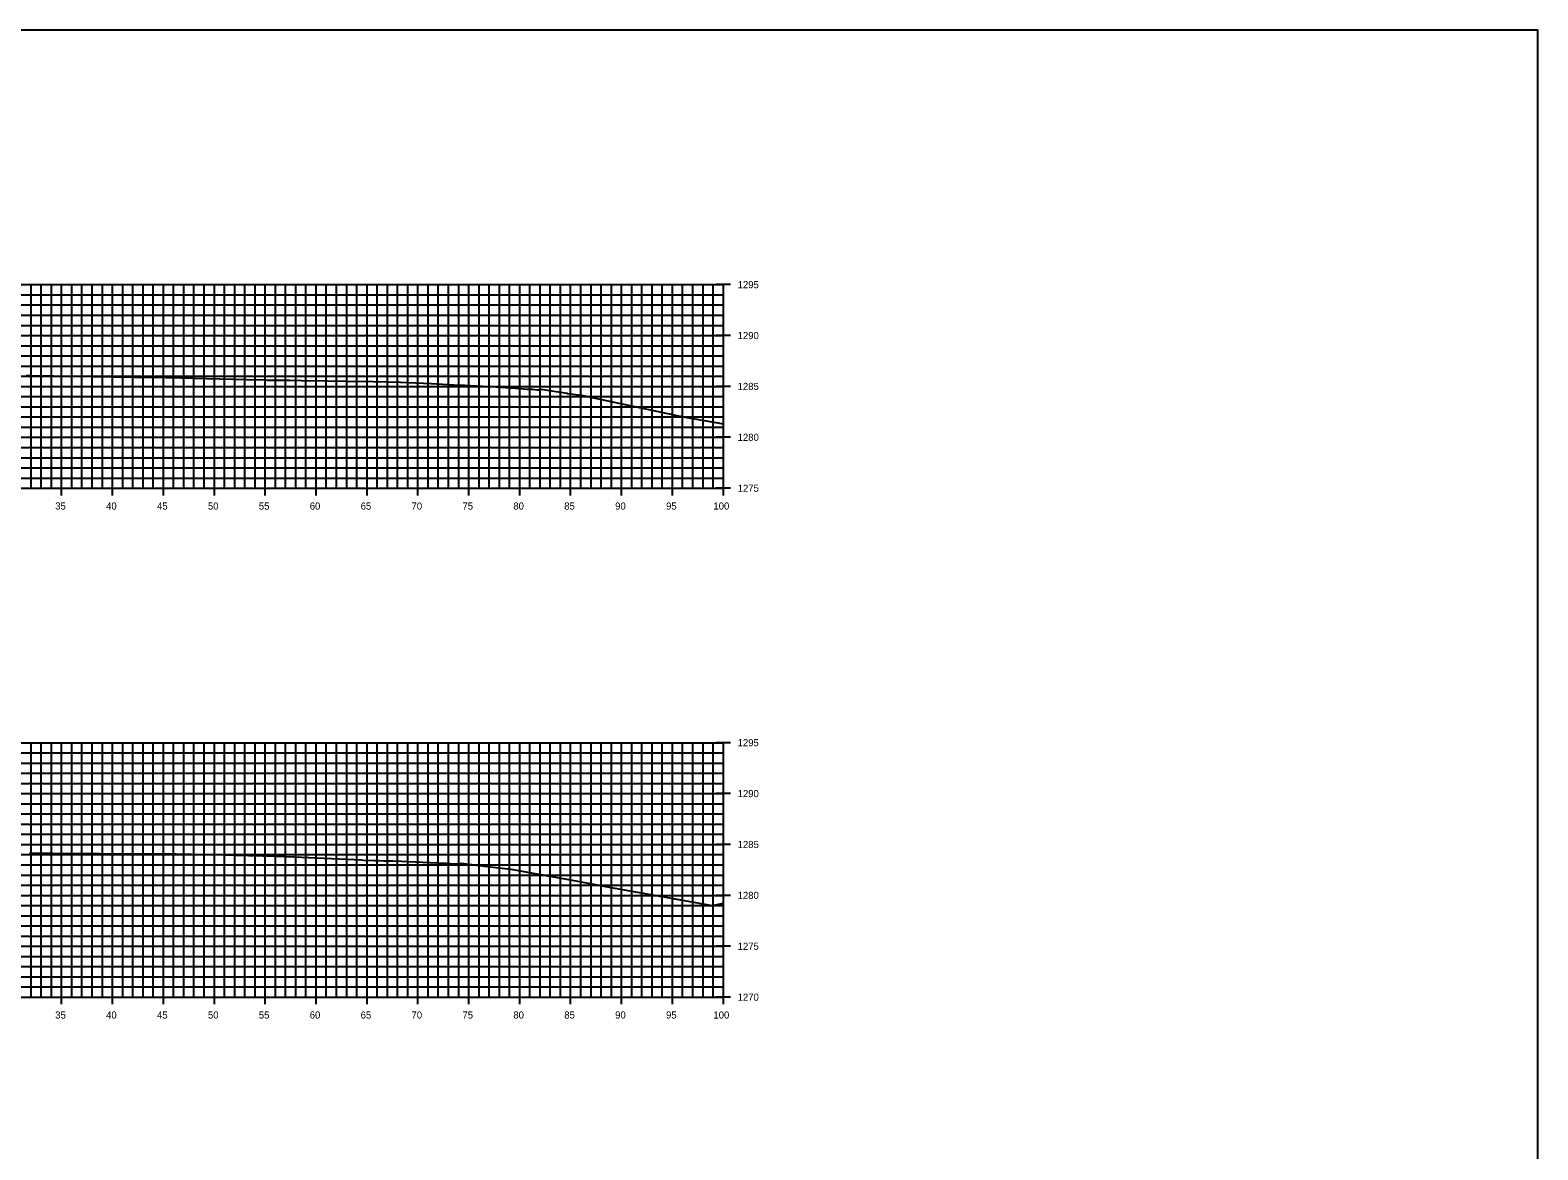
# Model space of a CAD drawing. Extents: x 674939 to 678919, y 750652 to 765176.
# Drawn here: x 678770.4 to 678918.5, y 757472.6 to 757582.6 of the extents above; entities that cross this region are included whole.
import ezdxf

# ---------------------------------------------------------------- set-up
doc = ezdxf.new("R2010")
doc.units = 0
for name, color, linetype in [('R_Axis', 7, 'Continuous'), ('R_Axis Annot', 7, 'Continuous'), ('R_Exist Surface', 7, 'Continuous'), ('R_Grid', 7, 'Continuous'), ('R_No Plot', 7, 'Continuous')]:
    doc.layers.add(name, color=color, linetype=linetype)

msp = doc.modelspace()

# ---------------------------------------------------------------- linework, layer by layer
at = {"layer": 'R_Axis'}
for p, q in [((678839.23, 757557.55), (678837.83, 757557.55)), ((678838.53, 757537.55), (678838.53, 757557.55)), ((678839.23, 757552.55), (678837.83, 757552.55)), ((678839.23, 757547.55), (678837.83, 757547.55)), ((678839.23, 757542.55), (678837.83, 757542.55)), ((678638.53, 757537.55), (678838.53, 757537.55)), ((678773.53, 757536.85), (678773.53, 757538.25)), ((678778.53, 757536.85), (678778.53, 757538.25)), ((678783.53, 757536.85), (678783.53, 757538.25)), ((678788.53, 757536.85), (678788.53, 757538.25)), ((678793.53, 757536.85), (678793.53, 757538.25)), ((678798.53, 757536.85), (678798.53, 757538.25)), ((678803.53, 757536.85), (678803.53, 757538.25)), ((678808.53, 757536.85), (678808.53, 757538.25)), ((678813.53, 757536.85), (678813.53, 757538.25)), ((678818.53, 757536.85), (678818.53, 757538.25)), ((678823.53, 757536.85), (678823.53, 757538.25)), ((678828.53, 757536.85), (678828.53, 757538.25)), ((678833.53, 757536.85), (678833.53, 757538.25)), ((678839.23, 757537.55), (678837.83, 757537.55)), ((678838.53, 757536.85), (678838.53, 757538.25)), ((678839.23, 757512.55), (678837.83, 757512.55)), ((678838.53, 757487.55), (678838.53, 757512.55)), ((678839.23, 757507.55), (678837.83, 757507.55)), ((678839.23, 757502.55), (678837.83, 757502.55)), ((678839.23, 757497.55), (678837.83, 757497.55)), ((678839.23, 757492.55), (678837.83, 757492.55)), ((678638.53, 757487.55), (678838.53, 757487.55)), ((678773.53, 757486.85), (678773.53, 757488.25)), ((678778.53, 757486.85), (678778.53, 757488.25)), ((678783.53, 757486.85), (678783.53, 757488.25)), ((678788.53, 757486.85), (678788.53, 757488.25)), ((678793.53, 757486.85), (678793.53, 757488.25)), ((678798.53, 757486.85), (678798.53, 757488.25)), ((678803.53, 757486.85), (678803.53, 757488.25)), ((678808.53, 757486.85), (678808.53, 757488.25)), ((678813.53, 757486.85), (678813.53, 757488.25)), ((678818.53, 757486.85), (678818.53, 757488.25)), ((678823.53, 757486.85), (678823.53, 757488.25)), ((678828.53, 757486.85), (678828.53, 757488.25)), ((678833.53, 757486.85), (678833.53, 757488.25)), ((678839.23, 757487.55), (678837.83, 757487.55)), ((678838.53, 757486.85), (678838.53, 757488.25))]:
    msp.add_line(p, q, dxfattribs=at)
at = {"layer": 'R_Exist Surface'}
for points in [[(678770.07, 757548.64), (678770.54, 757548.63), (678771.7, 757548.6), (678771.89, 757548.6), (678772.17, 757548.59), (678772.74, 757548.58), (678776.45, 757548.53), (678780.68, 757548.47), (678780.89, 757548.47), (678781.95, 757548.45), (678782.91, 757548.45), (678783.75, 757548.44), (678785.24, 757548.4), (678787.77, 757548.34), (678791.72, 757548.24), (678793.5, 757548.19), (678793.72, 757548.18), (678794.02, 757548.18), (678794.74, 757548.16), (678795.93, 757548.15), (678797.12, 757548.13), (678799.66, 757548.1), (678801.46, 757548.07), (678804.13, 757548.02), (678806.83, 757547.97), (678809.82, 757547.83), (678812.61, 757547.69), (678813.12, 757547.66), (678813.45, 757547.64), (678813.69, 757547.63), (678816.16, 757547.5), (678818.61, 757547.36), (678819.25, 757547.28), (678819.58, 757547.29), (678819.77, 757547.28), (678820.24, 757547.22), (678820.42, 757547.22), (678820.61, 757547.2), (678820.61, 757547.25), (678820.61, 757547.28), (678823.2, 757546.89), (678823.2, 757546.85), (678824.59, 757546.7), (678826.1, 757546.37), (678834.74, 757544.54), (678838.53, 757543.88)], [(678770.39, 757501.7), (678772.66, 757501.69), (678781.79, 757501.63), (678781.95, 757501.63), (678782.43, 757501.63), (678783.39, 757501.64), (678784.74, 757501.62), (678789.39, 757501.54), (678790.5, 757501.51), (678794.67, 757501.4), (678795.58, 757501.36), (678802.31, 757501.06), (678802.99, 757501.03), (678803.15, 757501.02), (678804.27, 757500.97), (678804.65, 757500.97), (678805.17, 757500.95), (678806.07, 757500.94), (678806.9, 757500.9), (678811.07, 757500.73), (678811.23, 757500.71), (678811.31, 757500.71), (678812.11, 757500.64), (678812.15, 757500.65), (678812.18, 757500.65), (678812.66, 757500.68), (678812.82, 757500.71), (678812.82, 757500.71), (678815.07, 757500.41), (678817.66, 757500.13), (678824.03, 757498.98), (678827.32, 757498.37), (678834.5, 757497.07), (678837.44, 757496.55), (678838.53, 757496.79)]]:
    msp.add_lwpolyline(points, dxfattribs=at)
at = {"layer": 'R_Grid'}
for p, q in [((678638.53, 757557.55), (678838.53, 757557.55)), ((678770.53, 757537.55), (678770.53, 757557.55)), ((678771.53, 757537.55), (678771.53, 757557.55)), ((678772.53, 757537.55), (678772.53, 757557.55)), ((678773.53, 757537.55), (678773.53, 757557.55)), ((678774.53, 757537.55), (678774.53, 757557.55)), ((678775.53, 757537.55), (678775.53, 757557.55)), ((678776.53, 757537.55), (678776.53, 757557.55)), ((678777.53, 757537.55), (678777.53, 757557.55)), ((678778.53, 757537.55), (678778.53, 757557.55)), ((678779.53, 757537.55), (678779.53, 757557.55)), ((678780.53, 757537.55), (678780.53, 757557.55)), ((678781.53, 757537.55), (678781.53, 757557.55)), ((678782.53, 757537.55), (678782.53, 757557.55)), ((678783.53, 757537.55), (678783.53, 757557.55)), ((678784.53, 757537.55), (678784.53, 757557.55)), ((678785.53, 757537.55), (678785.53, 757557.55)), ((678786.53, 757537.55), (678786.53, 757557.55)), ((678787.53, 757537.55), (678787.53, 757557.55)), ((678788.53, 757537.55), (678788.53, 757557.55)), ((678789.53, 757537.55), (678789.53, 757557.55)), ((678790.53, 757537.55), (678790.53, 757557.55)), ((678791.53, 757537.55), (678791.53, 757557.55)), ((678792.53, 757537.55), (678792.53, 757557.55)), ((678793.53, 757537.55), (678793.53, 757557.55)), ((678794.53, 757537.55), (678794.53, 757557.55)), ((678795.53, 757537.55), (678795.53, 757557.55)), ((678796.53, 757537.55), (678796.53, 757557.55)), ((678797.53, 757537.55), (678797.53, 757557.55)), ((678798.53, 757537.55), (678798.53, 757557.55)), ((678799.53, 757537.55), (678799.53, 757557.55)), ((678800.53, 757537.55), (678800.53, 757557.55)), ((678801.53, 757537.55), (678801.53, 757557.55)), ((678802.53, 757537.55), (678802.53, 757557.55)), ((678803.53, 757537.55), (678803.53, 757557.55)), ((678804.53, 757537.55), (678804.53, 757557.55)), ((678805.53, 757537.55), (678805.53, 757557.55)), ((678806.53, 757537.55), (678806.53, 757557.55)), ((678807.53, 757537.55), (678807.53, 757557.55)), ((678808.53, 757537.55), (678808.53, 757557.55)), ((678809.53, 757537.55), (678809.53, 757557.55)), ((678810.53, 757537.55), (678810.53, 757557.55)), ((678811.53, 757537.55), (678811.53, 757557.55)), ((678812.53, 757537.55), (678812.53, 757557.55)), ((678813.53, 757537.55), (678813.53, 757557.55)), ((678814.53, 757537.55), (678814.53, 757557.55)), ((678815.53, 757537.55), (678815.53, 757557.55)), ((678816.53, 757537.55), (678816.53, 757557.55)), ((678817.53, 757537.55), (678817.53, 757557.55)), ((678818.53, 757537.55), (678818.53, 757557.55)), ((678819.53, 757537.55), (678819.53, 757557.55)), ((678820.53, 757537.55), (678820.53, 757557.55)), ((678821.53, 757537.55), (678821.53, 757557.55)), ((678822.53, 757537.55), (678822.53, 757557.55)), ((678823.53, 757537.55), (678823.53, 757557.55)), ((678824.53, 757537.55), (678824.53, 757557.55)), ((678825.53, 757537.55), (678825.53, 757557.55)), ((678826.53, 757537.55), (678826.53, 757557.55)), ((678827.53, 757537.55), (678827.53, 757557.55)), ((678828.53, 757537.55), (678828.53, 757557.55)), ((678829.53, 757537.55), (678829.53, 757557.55)), ((678830.53, 757537.55), (678830.53, 757557.55)), ((678831.53, 757537.55), (678831.53, 757557.55)), ((678832.53, 757537.55), (678832.53, 757557.55)), ((678833.53, 757537.55), (678833.53, 757557.55)), ((678834.53, 757537.55), (678834.53, 757557.55)), ((678835.53, 757537.55), (678835.53, 757557.55)), ((678836.53, 757537.55), (678836.53, 757557.55)), ((678837.53, 757537.55), (678837.53, 757557.55)), ((678838.53, 757537.55), (678838.53, 757557.55)), ((678638.53, 757556.55), (678838.53, 757556.55)), ((678638.53, 757555.55), (678838.53, 757555.55)), ((678638.53, 757554.55), (678838.53, 757554.55)), ((678638.53, 757553.55), (678838.53, 757553.55)), ((678638.53, 757552.55), (678838.53, 757552.55)), ((678638.53, 757551.55), (678838.53, 757551.55)), ((678638.53, 757550.55), (678838.53, 757550.55)), ((678638.53, 757549.55), (678838.53, 757549.55)), ((678638.53, 757548.55), (678838.53, 757548.55)), ((678638.53, 757547.55), (678838.53, 757547.55)), ((678638.53, 757546.55), (678838.53, 757546.55)), ((678638.53, 757545.55), (678838.53, 757545.55)), ((678638.53, 757544.55), (678838.53, 757544.55)), ((678638.53, 757543.55), (678838.53, 757543.55)), ((678638.53, 757542.55), (678838.53, 757542.55)), ((678638.53, 757541.55), (678838.53, 757541.55)), ((678638.53, 757540.55), (678838.53, 757540.55)), ((678638.53, 757539.55), (678838.53, 757539.55)), ((678638.53, 757538.55), (678838.53, 757538.55)), ((678638.53, 757537.55), (678838.53, 757537.55)), ((678638.53, 757512.55), (678838.53, 757512.55)), ((678770.53, 757487.55), (678770.53, 757512.55)), ((678771.53, 757487.55), (678771.53, 757512.55)), ((678772.53, 757487.55), (678772.53, 757512.55)), ((678773.53, 757487.55), (678773.53, 757512.55)), ((678774.53, 757487.55), (678774.53, 757512.55)), ((678775.53, 757487.55), (678775.53, 757512.55)), ((678776.53, 757487.55), (678776.53, 757512.55)), ((678777.53, 757487.55), (678777.53, 757512.55)), ((678778.53, 757487.55), (678778.53, 757512.55)), ((678779.53, 757487.55), (678779.53, 757512.55)), ((678780.53, 757487.55), (678780.53, 757512.55)), ((678781.53, 757487.55), (678781.53, 757512.55)), ((678782.53, 757487.55), (678782.53, 757512.55)), ((678783.53, 757487.55), (678783.53, 757512.55)), ((678784.53, 757487.55), (678784.53, 757512.55)), ((678785.53, 757487.55), (678785.53, 757512.55)), ((678786.53, 757487.55), (678786.53, 757512.55)), ((678787.53, 757487.55), (678787.53, 757512.55)), ((678788.53, 757487.55), (678788.53, 757512.55)), ((678789.53, 757487.55), (678789.53, 757512.55)), ((678790.53, 757487.55), (678790.53, 757512.55)), ((678791.53, 757487.55), (678791.53, 757512.55)), ((678792.53, 757487.55), (678792.53, 757512.55)), ((678793.53, 757487.55), (678793.53, 757512.55)), ((678794.53, 757487.55), (678794.53, 757512.55)), ((678795.53, 757487.55), (678795.53, 757512.55)), ((678796.53, 757487.55), (678796.53, 757512.55)), ((678797.53, 757487.55), (678797.53, 757512.55)), ((678798.53, 757487.55), (678798.53, 757512.55)), ((678799.53, 757487.55), (678799.53, 757512.55)), ((678800.53, 757487.55), (678800.53, 757512.55)), ((678801.53, 757487.55), (678801.53, 757512.55)), ((678802.53, 757487.55), (678802.53, 757512.55)), ((678803.53, 757487.55), (678803.53, 757512.55)), ((678804.53, 757487.55), (678804.53, 757512.55)), ((678805.53, 757487.55), (678805.53, 757512.55)), ((678806.53, 757487.55), (678806.53, 757512.55)), ((678807.53, 757487.55), (678807.53, 757512.55)), ((678808.53, 757487.55), (678808.53, 757512.55)), ((678809.53, 757487.55), (678809.53, 757512.55)), ((678810.53, 757487.55), (678810.53, 757512.55)), ((678811.53, 757487.55), (678811.53, 757512.55)), ((678812.53, 757487.55), (678812.53, 757512.55)), ((678813.53, 757487.55), (678813.53, 757512.55)), ((678814.53, 757487.55), (678814.53, 757512.55)), ((678815.53, 757487.55), (678815.53, 757512.55)), ((678816.53, 757487.55), (678816.53, 757512.55)), ((678817.53, 757487.55), (678817.53, 757512.55)), ((678818.53, 757487.55), (678818.53, 757512.55)), ((678819.53, 757487.55), (678819.53, 757512.55)), ((678820.53, 757487.55), (678820.53, 757512.55)), ((678821.53, 757487.55), (678821.53, 757512.55)), ((678822.53, 757487.55), (678822.53, 757512.55)), ((678823.53, 757487.55), (678823.53, 757512.55)), ((678824.53, 757487.55), (678824.53, 757512.55)), ((678825.53, 757487.55), (678825.53, 757512.55)), ((678826.53, 757487.55), (678826.53, 757512.55)), ((678827.53, 757487.55), (678827.53, 757512.55)), ((678828.53, 757487.55), (678828.53, 757512.55)), ((678829.53, 757487.55), (678829.53, 757512.55)), ((678830.53, 757487.55), (678830.53, 757512.55)), ((678831.53, 757487.55), (678831.53, 757512.55)), ((678832.53, 757487.55), (678832.53, 757512.55)), ((678833.53, 757487.55), (678833.53, 757512.55)), ((678834.53, 757487.55), (678834.53, 757512.55)), ((678835.53, 757487.55), (678835.53, 757512.55)), ((678836.53, 757487.55), (678836.53, 757512.55)), ((678837.53, 757487.55), (678837.53, 757512.55)), ((678838.53, 757487.55), (678838.53, 757512.55)), ((678638.53, 757511.55), (678838.53, 757511.55)), ((678638.53, 757510.55), (678838.53, 757510.55)), ((678638.53, 757509.55), (678838.53, 757509.55)), ((678638.53, 757508.55), (678838.53, 757508.55)), ((678638.53, 757507.55), (678838.53, 757507.55)), ((678638.53, 757506.55), (678838.53, 757506.55)), ((678638.53, 757505.55), (678838.53, 757505.55)), ((678638.53, 757504.55), (678838.53, 757504.55)), ((678638.53, 757503.55), (678838.53, 757503.55)), ((678638.53, 757502.55), (678838.53, 757502.55)), ((678638.53, 757501.55), (678838.53, 757501.55)), ((678638.53, 757500.55), (678838.53, 757500.55)), ((678638.53, 757499.55), (678838.53, 757499.55)), ((678638.53, 757498.55), (678838.53, 757498.55)), ((678638.53, 757497.55), (678838.53, 757497.55)), ((678638.53, 757496.55), (678838.53, 757496.55)), ((678638.53, 757495.55), (678838.53, 757495.55)), ((678638.53, 757494.55), (678838.53, 757494.55)), ((678638.53, 757493.55), (678838.53, 757493.55)), ((678638.53, 757492.55), (678838.53, 757492.55)), ((678638.53, 757491.55), (678838.53, 757491.55)), ((678638.53, 757490.55), (678838.53, 757490.55)), ((678638.53, 757489.55), (678838.53, 757489.55)), ((678638.53, 757488.55), (678838.53, 757488.55)), ((678638.53, 757487.55), (678838.53, 757487.55))]:
    msp.add_line(p, q, dxfattribs=at)
at = {"layer": 'R_No Plot'}
msp.add_lwpolyline([(678578.53, 757362.55), (678918.53, 757362.55), (678918.53, 757582.55), (678578.53, 757582.55)], close=True, dxfattribs=at)

# ---------------------------------------------------------------- texts
at = {"layer": 'R_Axis Annot'}
for s, p in [('1295', (678839.93, 757557.2)), ('1290', (678839.93, 757552.2)), ('1285', (678839.93, 757547.2)), ('1280', (678839.93, 757542.2)), ('1275', (678839.93, 757537.2)), ('35', (678772.9, 757535.45)), ('40', (678777.9, 757535.45)), ('45', (678782.9, 757535.45)), ('50', (678787.9, 757535.45)), ('55', (678792.9, 757535.45)), ('60', (678797.9, 757535.45)), ('65', (678802.9, 757535.45)), ('70', (678807.9, 757535.45)), ('75', (678812.9, 757535.45)), ('80', (678817.9, 757535.45)), ('85', (678822.9, 757535.45)), ('90', (678827.9, 757535.45)), ('95', (678832.9, 757535.45)), ('100', (678837.55, 757535.45)), ('1295', (678839.93, 757512.2)), ('1290', (678839.93, 757507.2)), ('1285', (678839.93, 757502.2)), ('1280', (678839.93, 757497.2)), ('1275', (678839.93, 757492.2)), ('1270', (678839.93, 757487.2)), ('35', (678772.9, 757485.45)), ('40', (678777.9, 757485.45)), ('45', (678782.9, 757485.45)), ('50', (678787.9, 757485.45)), ('55', (678792.9, 757485.45)), ('60', (678797.9, 757485.45)), ('65', (678802.9, 757485.45)), ('70', (678807.9, 757485.45)), ('75', (678812.9, 757485.45)), ('80', (678817.9, 757485.45)), ('85', (678822.9, 757485.45)), ('90', (678827.9, 757485.45)), ('95', (678832.9, 757485.45)), ('100', (678837.55, 757485.45))]:
    msp.add_text(s, height=0.7, dxfattribs=at).set_placement(p)

doc.saveas('drawing.dxf')
